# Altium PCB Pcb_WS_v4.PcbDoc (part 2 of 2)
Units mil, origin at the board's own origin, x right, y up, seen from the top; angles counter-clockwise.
Board outline 3890 x 3890 mil, 2 copper layers (Top Layer, Bottom Layer), stack 50.044 mil thick; 84 components, 65 nets, 260 pads, 445 vias.
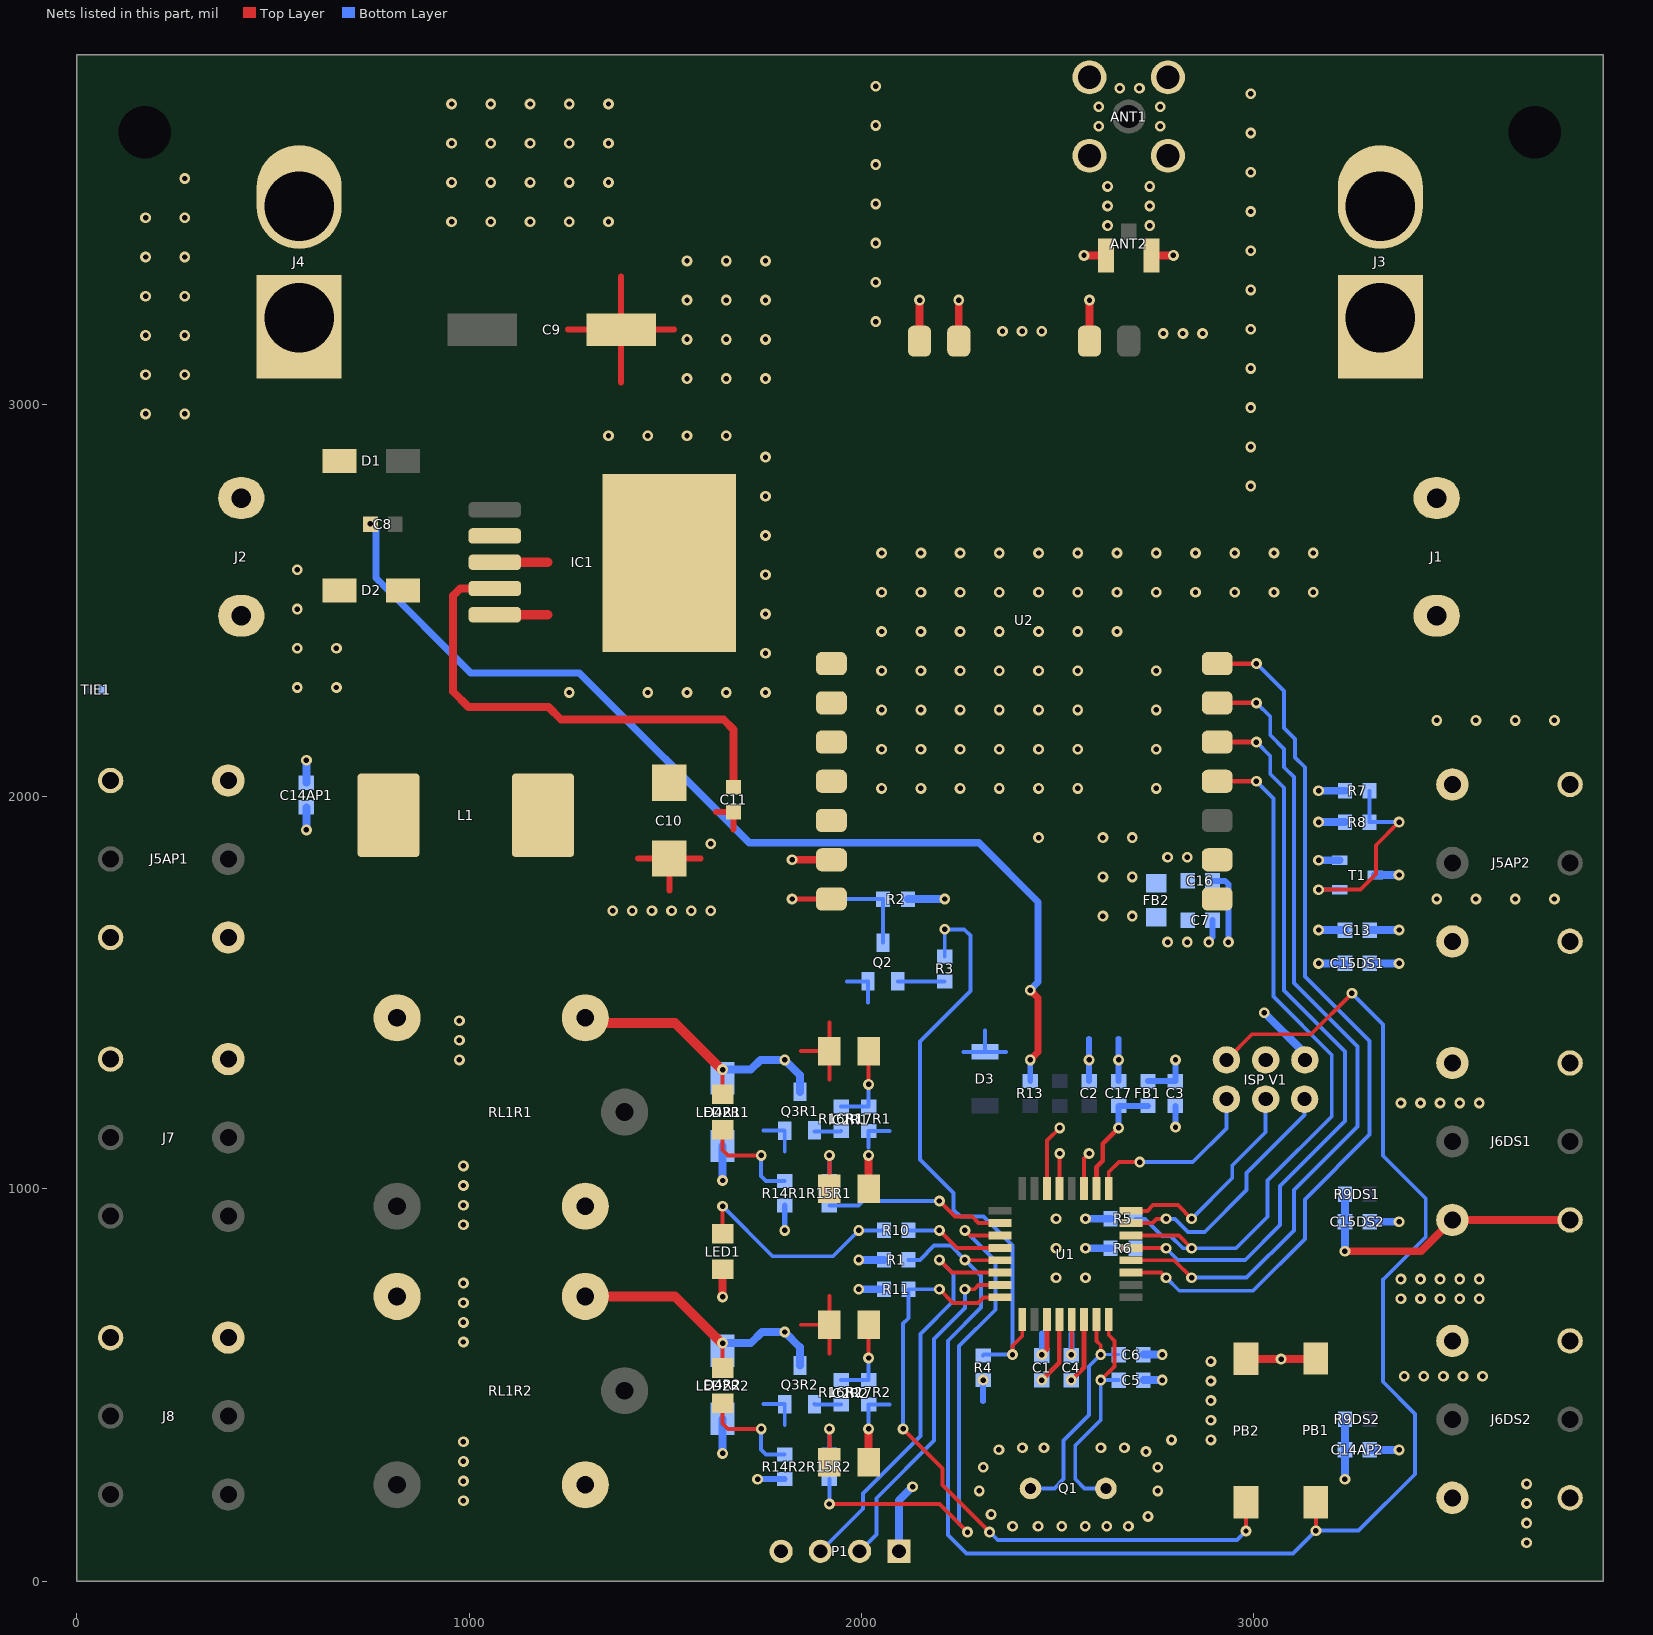
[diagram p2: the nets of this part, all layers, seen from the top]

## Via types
v1: diameter 27.56, hole 13.78, Top Layer to Bottom Layer, tented both sides, 369 vias
v2: diameter 20, hole 11.81, Top Layer to Bottom Layer, tented both sides, 76 vias

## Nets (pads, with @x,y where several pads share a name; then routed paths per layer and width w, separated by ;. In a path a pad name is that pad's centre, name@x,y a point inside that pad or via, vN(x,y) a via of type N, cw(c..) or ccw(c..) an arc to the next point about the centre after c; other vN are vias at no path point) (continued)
GND: "ISP V1.5" C1.2 C2.1 C3.2 C4.2 C5.2 C6.2 C7.1 C8.2 C9.2 C10.2 C11.2 C13.2 C14AP1.1 C14AP2.1 C15DS1.1 C15DS2.1 C16.1 C17.1 D2.2 D3.2 IC1.3 IC1.5 IC1.6 IC2R1.2 IC2R2.2 J2.1 J4.1 J5AP1.3 J5AP2.3 J6DS1.3 J6DS2.3 LED1.2 P1.4 PB1.2 PB2.2 Q2.2 Q3R1.2 Q3R2.2 R4.1 R5.2 R6.2 R7.1 R13.2 R17R1.1 R17R2.1 TIE1.1 U1.3 U1.5 U1.21 U2.7 U2.9 | length 6601.5
  Top Layer w9.84: U1.21@2504.06,1000.59 2504.06,1089.06 v1(2505,1090) ; v1(2534.61,577.18) 2535.55,578.13 U1.5@2535.55,666.59
  Top Layer w12: v1(2459.61,577.18) 2472.56,590.13 U1.3@2472.56,666.59
  Top Layer w15: 1251.93,3190 C9.2@1387.17,3190 ; 1387.17,3054.77 C9.2@1387.17,3190 ; 1387.17,3325.23 C9.2@1387.17,3190 ; 1430,1842.04 C10.2@1510,1842.04 1590,1842.04 ; 1510.45,1759.93 C10.2@1510.45,1839.93 ; 1522.4,3190 C9.2@1387.17,3190 ; 1629.05,1960.5 C11.2@1673.55,1960.5 1673.55,1916
  Top Layer w18: v1(2430,1328.39) 2450,1348.39 2450,1377.69 2450,1486 v1(2430,1506)
  Top Layer w20: v1(1645.86,724.46) LED1.2@1645.86,795 ; v1(1822.96,1838.49) U2.9@1922.96,1838.49 ; IC2R2.2@2017.86,303.06 v1(2017.86,387.87) ; IC2R1.2@2017.86,1000.34 v1(2017.86,1085.15) ; PB2.2@2979.87,566.56 2980.72,565.7 v1(3069.31,565.7) 3156.27,565.7 PB1.2@3157.89,567.33
  Top Layer w25: IC1.5@1065.04,2463.1 1200.27,2463.1 ; IC1.3@1065.04,2596.96 1200.27,2596.96
  Bottom Layer w10: 1750.16,451.1 Q3R2.2@1804.06,451.1 1804.06,397.2 ; 1750.16,1148.38 Q3R1.2@1804.06,1148.38 1804.06,1094.48 ; 1962.5,1528.58 Q2.2@2016.4,1528.58 2016.4,1474.68 ; v1(2017.86,387.87) R17R2.1@2017.86,449.74 2071.76,449.74 ; 2017.86,1105.65 R17R1.1@2017.86,1147.02 2071.76,1147.02 ; 2260.17,1349.12 D3.2@2314.07,1349.12 ; 2314.07,1403.02 D3.2@2314.07,1349.12 ; 2367.98,1349.12 D3.2@2314.07,1349.12
  Bottom Layer w15: 2309.61,458.28 v1(2309.61,512.18) ; R13.2@2430,1274.31 v1(2430,1328.39) ; v1(2459.61,577.18) 2459.61,631.08 ; v1(2534.61,577.18) 2534.61,631.08 ; C2.1@2580,1274.31 v1(2580,1328.39) 2580,1382.47 ; C17.1@2655,1274.32 v1(2655,1328.39) 2655,1382.47 ; v1(2800,1157.24) C3.2@2800,1211.32 ; v1(2885,1628.77) 2885,1632.17 2894.28,1641.44 C7.1@2894.28,1684.95 ; C16.1@2894.28,1784.92 2926.21,1784.92 2935,1776.13 v1(2935,1628.77)
  Bottom Layer w18: v1(748,2694.78) 748,2693.46 762,2679.46 762,2556.74 1003.74,2315 1280.5,2315 1713.5,1882 2299.33,1882 2450,1731.33 2450,1526.7 2430,1506.7 v1(2430,1506)
  Bottom Layer w20: C14AP1.1@585,2035 v1(585,2092.32) ; v1(2570.81,848.39) R6.2@2634.67,848.39 ; v1(2570.81,923.39) R5.2@2634.67,923.39 ; C5.2@2718.3,512.18 v1(2766.21,512.18) ; C6.2@2718.3,577.18 v1(2766.21,577.18) ; v1(3165,1574.46) C15DS1.1@3232.01,1574.46 ; v1(3165,1659.46) C13.2@3232.01,1659.46 ; v1(3165,2014.46) R7.1@3232.01,2014.46 ; C14AP2.1@3295,334.46 v1(3370,334.46) ; C15DS2.1@3295,915.77 v1(3370,915.77)
  other v1: 2385,140 2450,140 2510,140 2570,140 2625,140 2680,140 2730,165 2330,170 985,205 2300,230 2755,230 985,255 2310,290 2755,290 985,305 2725,330 2350,335 2410,340 2465,340 2610,340 2670,340 985,355 2790,360 2890.32,360.02 2890.32,410.02 2890.32,460.02 2890.32,510.02 3383,522 3433,522 3483,522 3533,522 3583,522 2890.32,560.02 985,609.51 985,659.51 985,709.51 3374.51,719.61 3424.51,719.61 3474.51,719.61 3524.51,719.61 3574.51,719.61 985,759.51 3374.51,769.61 3424.51,769.61 3474.51,769.61 3524.51,769.61 3574.51,769.61 2495.81,773.39 2570.81,773.39 2495.81,848.39 985,908.21 2495.81,923.39 985,958.21 985,1008.21 985,1058.21 3374.51,1218.65 3424.51,1218.65 3474.51,1218.65 3524.51,1218.65 3574.51,1218.65 975,1328.39 975,1378.39 975,1428.39 2615,1695 2690,1695 1365.62,1708.72 1415.62,1708.72 1465.62,1708.72 1515.62,1708.72 1565.62,1708.72 1615.62,1708.72 3465.86,1738.49 3565.86,1738.49 3665.86,1738.49 3765.86,1738.49 2615,1795 2690,1795 1615.62,1879.25 2451.06,1895 2615,1895 2690,1895 2051.06,2020.48 2151.06,2020.48 2251.06,2020.48 2351.06,2020.48 2451.06,2020.48 2551.06,2020.48 2751.06,2020.48 2051.06,2120.48 2151.06,2120.48 2251.06,2120.48 2351.06,2120.48 2451.06,2120.48 2551.06,2120.48 2751.06,2120.48 3465.86,2193.71 3565.86,2193.71 3665.86,2193.71 3765.86,2193.71 2051.06,2220.48 2151.06,2220.48 2251.06,2220.48 2351.06,2220.48 2451.06,2220.48 2551.06,2220.48 2751.06,2220.48 1255,2265 1455,2265 1555,2265 1655,2265 1755,2265 561.41,2277.57 661.41,2277.57 2051.06,2320.48 2151.06,2320.48 2251.06,2320.48 2351.06,2320.48 2451.06,2320.48 2551.06,2320.48 2751.06,2320.48 1755,2365 561.41,2377.57 661.41,2377.57 2051.06,2420.48 2151.06,2420.48 2251.06,2420.48 2351.06,2420.48 2451.06,2420.48 2551.06,2420.48 2651.06,2420.48 1755,2465 561.41,2477.57 2051.06,2520.48 2151.06,2520.48 2251.06,2520.48 2351.06,2520.48 2451.06,2520.48 2551.06,2520.48 2651.06,2520.48 2751.06,2520.48 2851.06,2520.48 2951.06,2520.48 3051.06,2520.48 3151.06,2520.48 1755,2565 561.41,2577.57 2051.06,2620.48 2151.06,2620.48 2251.06,2620.48 2351.06,2620.48 2451.06,2620.48 2551.06,2620.48 2651.06,2620.48 2751.06,2620.48 2851.06,2620.48 2951.06,2620.48 3051.06,2620.48 3151.06,2620.48 1755,2665 1755,2765 1755,2865 1355,2919.51 1455,2919.51 1555,2919.51 1655,2919.51 175,2975 275,2975 1555,3065 1655,3065 1755,3065 175,3075 275,3075 1555,3165 1655,3165 1755,3165 175,3175 275,3175 1555,3265 1655,3265 1755,3265 175,3275 275,3275 1555,3365 1655,3365 1755,3365 175,3375 275,3375 955,3465 1055,3465 1155,3465 1255,3465 1355,3465 175,3475 275,3475 955,3565 1055,3565 1155,3565 1255,3565 1355,3565 275,3575 955,3665 1055,3665 1155,3665 1255,3665 1355,3665 955,3765 1055,3765 1155,3765 1255,3765 1355,3765
GND-SOLAR: J1.2 J3.1
GND_ANT: ANT1.2 ANT2.2 U2.15 U2.16 U2.17 | length 425.1
  Top Layer w20: U2.15@2147.76,3160.54 v1(2147.76,3265) ; U2.16@2247.76,3160.54 v1(2247.76,3265) ; v1(2566.92,3379) ANT2.2@2622.76,3379 ; U2.17@2580.84,3160.54 v1(2580.84,3265) ; ANT2.2@2738.91,3379 v1(2794.75,3379)
  other v1: 2992,2791 2992,2891 2992,2991 2992,3091 2769.1,3180.06 2819.1,3180.06 2869.1,3180.06 2359.16,3185.88 2409.16,3185.88 2459.16,3185.88 2992,3191 2035.94,3210.36 2992,3291 2035.94,3310.36 2992,3391 2035.94,3410.36 2627.07,3455 2734.27,3455 2992,3491 2627.07,3505 2734.27,3505 2035.94,3510.36 2627.07,3555 2734.27,3555 2992,3591 2035.94,3610.36 2992,3691 2604.38,3708.09 2761.22,3708.09 2035.94,3710.36 2604.38,3758.09 2761.22,3758.09 2992,3791 2658.24,3804.81 2708.24,3804.81 2035.94,3810.36
LED: R10.1 U1.28 | length 251.5
  Top Layer w10: v1(2198.39,893.79) 2242.84,849.34 U1.28@2352.8,849.34
  Bottom Layer w10: R10.1@2119.71,893.79 v1(2198.39,893.79)
M0: U1.11 U2.1 | length 2271.3
  Top Layer w10: U1.11@2686.8,786.35 2763.26,786.35 v1(2776.21,773.39)
  Top Layer w12: U2.1@2906.43,2338.49 v1(3006.43,2338.49)
  Bottom Layer w10: v1(2776.21,773.39) 2809.61,740 2997.76,740 3130,872.24 3130,972.99 3295,1137.99 3295,1376.3 3130,1541.3 3130,2074.32 3104.99,2099.33 3104.99,2146.3 3076.66,2174.62 3076.66,2268.26 v1(3006.43,2338.49)
M1: U1.12 U2.2 | length 2102
  Top Layer w10: U1.12@2686.8,817.84 2796.76,817.84 v1(2841.21,773.39)
  Top Layer w12: U2.2@2906.43,2238.49 v1(3006.43,2238.49)
  Bottom Layer w10: v1(2841.21,773.39) 2981.3,773.39 3101.84,893.93 3101.84,996.54 3264.2,1158.9 3264.2,1362.2 3101.84,1524.56 3101.84,2049.15 3076.66,2074.32 3076.66,2121.29 3041.54,2156.41 3041.54,2203.37 v1(3006.43,2238.49)
MISO: "ISP V1.2" U1.16 | length 558.1
  Top Layer w10: U1.16@2686.8,943.83 2728.65,943.83 2743.21,958.39 2806.21,958.39 v1(2841.21,923.39)
  Bottom Layer w10: v1(2841.21,923.39) 2944.82,1027 2944.82,1058.82 3030,1144 3030,1228.39
MOSI: "ISP V1.3" U1.15 | length 650
  Top Layer w10: U1.15@2686.8,912.33 2741.13,912.33 2752.19,923.39 v1(2776.21,923.39)
  Bottom Layer w10: v1(2776.21,923.39) 2798.31,923.39 2831.71,890 2874.61,890 2981.3,996.69 2981.3,1040.05 3129,1187.75 3129,1228.39
NetC16_2: C16.2 FB2.2 U2.6
  other v1: 2780,1845 2830,1845
NetC17_2: C17.2 FB1.2 U1.18 | length 309.1
  Top Layer w12: U1.18@2598.54,1000.59 2598.54,1054.92 2615,1071.38 2615,1115 v1(2655,1155)
  Bottom Layer w15: v1(2655,1155) C17.2@2655,1211.32 FB1.2@2730,1211.32
NetD2_1: D2.1 IC1.2 L1.1
NetD4R1_2: D4R1.2 LED2R1.2 Q3R1.3 RL1R1.4 | length 728.5
  Top Layer w10: LED2R1.2@1645.86,1240.54 v1(1645.86,1303.81)
  Top Layer w25: RL1R1.4@1295.86,1422.82 1524.46,1422.82 v1@1643.47,1303.81
  Bottom Layer w20: D4R1.2@1643.47,1303.81 v1(1645.86,1303.81) 1717.53,1303.81 1742.11,1328.39 v1(1804.06,1328.39) 1842.66,1289.8 Q3R1.3@1842.66,1246.8
NetD4R2_2: D4R2.2 LED2R2.2 Q3R2.3 RL1R2.4 | length 734
  Top Layer w10: LED2R2.2@1645.86,543.26 v1(1645.86,606.53)
  Top Layer w25: RL1R2.4@1295.86,725.54 1524.46,725.54 v1@1643.47,606.53
  Bottom Layer w20: D4R2.2@1643.47,606.53 1717.53,606.53 1746,635 v1(1804.06,635) 1842.66,596.4 Q3R2.3@1842.66,549.52
NetIC2R1_1: IC2R1.1 R15R1.2 | length 149.9
  Top Layer w10: IC2R1.1@1917.86,1000.34 v1(1917.86,1085.15)
  Bottom Layer w10: R15R1.2@1917.86,1020.01 v1(1917.86,1085.15)
NetIC2R2_1: IC2R2.1 R15R2.2 | length 149.9
  Top Layer w10: IC2R2.1@1917.86,303.06 v1(1917.86,387.87)
  Bottom Layer w10: R15R2.2@1917.86,322.73 v1(1917.86,387.87)
NetLED1_1: LED1.1 R10.2 | length 561.5
  Top Layer w10: LED1.1@1645.86,885 v1(1645.86,955.54)
  Bottom Layer w10: v1(1645.86,955.54) 1773.4,828 1927.07,828 v1(1992.86,893.79) R10.2@2056.72,893.79
NetLED2R1_1: LED2R1.1 R14R1.2 | length 273.2
  Top Layer w10: LED2R1.1@1645.86,1150.54 1645.86,1099.14 1659.86,1085.14 v1(1744.06,1085.14)
  Bottom Layer w10: v1(1744.06,1085.14) 1744.06,1032.6 1756.65,1020.01 R14R1.2@1804.06,1020.01
NetLED2R2_1: LED2R2.1 R14R2.2 | length 273.2
  Top Layer w10: LED2R2.1@1645.86,453.26 1645.86,401.86 1659.86,387.87 v1(1744.06,387.87)
  Bottom Layer w10: v1(1744.06,387.87) 1744.06,335.32 1756.65,322.73 R14R2.2@1804.06,322.73
NetQ2_1: Q2.1 R3.2 | length 119.9
  Bottom Layer w10: Q2.1@2092.2,1528.8 R3.2@2212.06,1528.8
NetQ3R1_1: Q3R1.1 R16R1.2 | length 68.4
  Bottom Layer w10: Q3R1.1@1879.86,1146.01 1946.85,1146.01 R16R1.2@1947.86,1147.02
NetQ3R2_1: Q3R2.1 R16R2.2 | length 68.7
  Bottom Layer w10: Q3R2.1@1879.86,451.31 1881.43,449.74 R16R2.2@1947.86,449.74
NetR7_2: R7.2 R8.2 T1.1 | length 527.4
  Top Layer w10: v1(3165,1762.33) 3271.14,1762.33 3311.13,1802.32 3311.13,1875.59 v1(3370,1934.46)
  Bottom Layer w10: v1(3165,1762.33) T1.1@3218.23,1762.33 ; R7.2@3295,2014.46 R8.2@3295,1934.46 v1(3370,1934.46)
NetU1_19: U1.19 | length 94.8
  Top Layer w10: U1.19@2567.05,1000.59 2567.05,1077.05 v1(2580,1090)
NetU1_22: U1.22 | length 167.8
  Top Layer w10: U1.22@2472.56,1000.59 2472.56,1122.56 v1(2505,1155)
NetU2_10: U2.10
NetU2_11: U2.11
NetU2_12: U2.12
NetU2_13: U2.13
NetU2_14: U2.14
OPEN1: J7.1 RL1R1.3
OPEN2: J8.1 RL1R2.3
P5V-Main: "ISP V1.6" C1.1 C3.1 C4.1 C7.2 C10.1 C11.1 D4R1.1 D4R2.1 FB1.1 FB2.1 IC1.4 IC2R1.4 IC2R2.4 L1.2 P1.1 R1.1 R2.2 R8.1 R11.1 R14R1.1 R14R2.1 RL1R1.5 RL1R2.5 T1.2 U1.4 U1.6 | length 3154.2
  Top Layer w10: 1845,653.46 IC2R2.4@1917.86,653.46 ; 1845,1350.74 IC2R1.4@1917.86,1350.74 ; 1917.86,580.6 IC2R2.4@1917.86,653.46 ; 1917.86,726.32 IC2R2.4@1917.86,653.46 ; 1917.86,1277.88 IC2R1.4@1917.86,1350.74 ; 1917.86,1423.59 IC2R1.4@1917.86,1350.74
  Top Layer w12: v1(2459.61,512.18) 2504.06,556.63 U1.4@2504.06,666.59 ; v1(2534.61,512.18) 2567.05,544.62 U1.6@2567.05,666.59
  Top Layer w20: IC1.4@1065.04,2530.03 977.03,2530.03 959,2512 959,2267.02 998.02,2228 1202,2228 1234.23,2195.77 1648.39,2195.77 1673.55,2170.61 C11.1@1673.55,2023.5
  Bottom Layer w15: v1(1735,259.74) R14R2.1@1804.06,259.74 ; v1(1804.06,893.79) R14R1.1@1804.06,957.02 ; FB1.1@2730,1274.32 C3.1@2800,1274.32 v1(2800,1328.39)
  Bottom Layer w20: v1(1645.86,325.47) D4R2.1@1645.86,413.39 ; v1(1645.86,1021.01) D4R1.1@1645.86,1108.93 ; v1(1992.86,743.79) R11.1@2056.72,743.79 ; v1(1992.86,818.79) R1.1@2056.72,818.79 ; P1.1@2095,76 2095,205.55 v1(2130,240.55) ; R2.2@2117.99,1738.49 v1(2212.06,1738.49) ; v1(3026.21,1448.39) 3130,1344.6 3130,1328.39 ; v1(3165,1837.14) T1.2@3218.23,1837.14 ; v1(3165,1934.46) R8.1@3232.01,1934.46
  other v1: 2780,1628.77 2830,1628.77
P5V-SEN: C13.1 C14AP1.2 C14AP2.2 C15DS1.2 C15DS2.2 J5AP1.1 J5AP2.1 J6DS1.1 J6DS2.1 R9DS1.2 R9DS2.2 T1.3 | length 1173.8
  Top Layer w20: v1(3232.01,840.77) 3426.09,840.77 J6DS1.1@3505.86,920.54 J6DS1.1@3805.86,920.54
  Bottom Layer w20: v1(585,1914.69) C14AP1.2@585,1972.01 ; v1(3232.01,259.46) C14AP2.2@3232.01,334.46 R9DS2.2@3232.01,412.26 ; v1(3232.01,840.77) C15DS2.2@3232.01,915.77 R9DS1.2@3232.01,986.31 ; C15DS1.2@3295,1574.46 v1(3370,1574.46) ; C13.1@3295,1659.46 v1(3370,1659.46) ; T1.3@3308.78,1799.74 v1(3370,1799.74)
  other v1: 3695,97.74 3695,147.74 3695,197.74 3695,247.74
P12V-BAT: D1.2 J2.2 J4.2
P16V-SOLAR: J1.1 J3.2
RESET-E32: R3.1 R4.2 U1.1 | length 1571.2
  Top Layer w10: v1(2384.61,577.18) 2384.61,599.79 2409.57,624.75 U1.1@2409.57,666.59
  Bottom Layer w9.84: R3.1@2212.06,1591.79 v1(2212.06,1661.26)
  Bottom Layer w10: v1(2212.06,1661.26) 2261.59,1661.26 2277.53,1645.32 2277.53,1503.75 2148.79,1375.01 2148.79,1074.97 2234.61,989.15 2234.61,945.77 2251.6,928.79 2311.16,928.79 2384.61,855.34 v1(2384.61,577.18) 2311.61,577.18 R4.2@2309.61,575.17
RL-CT-QR1: IC2R1.3 R16R1.1 R17R1.2 | length 210.7
  Top Layer w10: v1(2017.86,1265.93) IC2R1.3@2017.86,1350.74
  Bottom Layer w10: R16R1.1@1947.86,1210.01 R17R1.2@2017.86,1210.01 v1(2017.86,1265.93)
RL-CT-QR2: IC2R2.3 R16R2.1 R17R2.2 | length 210.7
  Top Layer w10: v1(2017.86,568.65) IC2R2.3@2017.86,653.46
  Bottom Layer w10: R16R2.1@1947.86,512.73 R17R2.2@2017.86,512.73 v1(2017.86,568.65)
RL-CTL1: R15R1.1 U1.26 | length 463.2
  Top Layer w10: v1(2198.39,968.79) 2238.39,928.79 2282.02,928.79 2298.48,912.33 U1.26@2352.8,912.33
  Bottom Layer w10: R15R1.1@1917.86,957.02 1991.67,957.02 2003.44,968.79 v1(2198.39,968.79)
RL-CTL2: R15R2.1 U1.27 | length 1388.2
  Top Layer w10: v1(1917.86,196.51) 2198.49,196.51 v1(2270,125) ; v1(2263.39,893.79) 2276.35,880.83 U1.27@2352.8,880.83
  Bottom Layer w10: v1(1917.86,196.51) R15R2.1@1917.86,259.74 ; v1(2263.39,893.79) 2341.63,815.55 2341.63,691.63 2248.78,598.78 2248.78,146.22 v1(2270,125)
RST-E32: Q2.3 R2.1 U2.8 | length 443.5
  Top Layer w12: v1(1822.96,1738.49) U2.8@1922.96,1738.49
  Bottom Layer w10: v1(1822.96,1738.49) R2.1@2055,1738.49 Q2.3@2055,1627.01
RST_MCU: "ISP V1.4" PB1.1 R1.2 U1.29 | length 4156.8
  Top Layer w10: v1(2263.39,818.79) 2264.34,817.84 U1.29@2352.8,817.84 ; 2930,1328.39 2995.41,1393.8 3145.26,1393.8 v1(3249.65,1498.2) ; v1(3157.89,128.46) PB1.1@3157.89,201.19
  Bottom Layer w10: R1.2@2119.71,818.79 2148.79,818.79 2185,855 2227.18,855 v1(2263.39,818.79) 2304.79,777.39 2304.79,697.4 2220,612.61 2220,117.62 2267.62,70 3099.43,70 v1(3157.89,128.46) 3266.66,128.46 3410.58,272.37 3410.58,426.31 3328.7,508.18 3328.7,768.19 3437.96,877.45 3437.96,975.04 3328.8,1084.19 3328.8,1419.05 v1(3249.65,1498.2)
RXD-E32: R6.1 U1.13 U2.3 | length 2000.7
  Top Layer w10: U1.13@2686.8,849.34 2775.27,849.34 v1(2776.21,848.39)
  Top Layer w12: U2.3@2906.43,2138.49 v1(3006.43,2138.49)
  Bottom Layer w10: R6.1@2697.66,848.39 v1(2776.21,848.39) 2805.82,818.79 2977.86,818.79 3067,907.92 3067,1007.31 3232.01,1172.32 3232.01,1350.17 3076.66,1505.51 3076.66,2022.11 3041.54,2057.22 3041.54,2103.37 v1(3006.43,2138.49)
RXM: P1.3 U1.30 | length 1066.3
  Top Layer w10: v1(2198.39,818.79) 2230.83,786.35 U1.30@2352.8,786.35
  Bottom Layer w10: P1.3@1895,76 2003.44,184.44 2003.44,223.44 2150,370 2150,630 2234.61,714.61 2234.61,782.57 v1(2198.39,818.79)
SCK: "ISP V1.1" U1.17 | length 462.4
  Top Layer w10: U1.17@2630.04,1000.59 2630.04,1042.43 2655.61,1068 v1(2709,1068)
  Bottom Layer w10: v1(2709,1068) 2844,1068 2930,1154 2930,1228.39
TXD-E32: R5.1 U1.14 U2.4 | length 1926.4
  Top Layer w10: U1.14@2686.8,880.83 2808.77,880.83 v1(2841.21,848.39)
  Top Layer w12: U2.4@2906.43,2038.49 v1(3006.43,2038.49)
  Bottom Layer w10: R5.1@2697.66,923.39 2722.59,923.39 2765.98,880 2787.28,880 2818.89,848.39 v1(2841.21,848.39) 2954.61,848.39 3034.9,928.69 3034.9,1020.64 3198.31,1184.04 3198.31,1341.29 3050,1489.6 3050,1994.92 v1(3006.43,2038.49)
TXM: P1.2 U1.31 | length 873
  Top Layer w10: v1(2263.39,743.79) 2287.41,743.79 2298.48,754.85 U1.31@2352.8,754.85
  Bottom Layer w10: P1.2@1995,76 2038.25,119.25 2038.25,211.2 2185,357.95 2185,617.5 2263.39,695.89 v1(2263.39,743.79)
WAKE: PB2.1 R11.2 U1.32 | length 1713.4
  Top Layer w10: v1(2105.83,387.87) 2206.2,287.5 2206.2,245.15 v1(2326.35,125) ; v1(2198.39,743.79) 2233.39,708.79 2296.39,708.79 2310.96,723.35 U1.32@2352.8,723.35 ; v1(2979.87,127.69) PB2.1@2979.87,200.42
  Bottom Layer w10: v1(2105.83,387.87) 2105.83,656.12 2119.71,670 R11.2@2119.71,743.79 v1(2198.39,743.79) ; v1(2326.35,125) 2327.05,125 2347.05,105 2957.17,105 v1(2979.87,127.69)
XTAL1: C6.1 Q1.1 U1.7 | length 590.6
  Top Layer w10: U1.7@2598.54,666.59 2598.54,612.26 2609.61,601.2 v1(2609.61,577.18)
  Bottom Layer w8: v1(2609.61,577.18) C6.1@2655.31,577.18
  Bottom Layer w10: Q1.1@2430.49,236.12 2491.32,236.12 2514.95,259.74 2514.95,358.04 2580,423.09 2580,547.57 v1(2609.61,577.18)
XTAL2: C5.1 Q1.2 U1.8 | length 587.9
  Top Layer w10: v1(2609.61,512.18) 2644.61,547.18 2644.61,612.26 2630.04,626.83 U1.8@2630.04,666.59
  Bottom Layer w10: Q1.2@2622.61,236.12 2568.17,236.12 2544.55,259.74 2544.55,345.77 2609.61,410.83 v1(2609.61,512.18) C5.1@2655.31,512.18
pads on no net: HOLE1.1 HOLE2.1

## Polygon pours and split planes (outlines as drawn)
GND on Top Layer "GND_L01_P027" (solid, remove dead copper, pour order 27): 1715,1900 1715,1992 1850,1992 1850,2675 1900,2675 1900,3855 35,3855 35,2250 650,2250 650,1650 1650,1650 1650,1900
GND on Top Layer "GND_L01_P039" (solid, pour order 39): 2747.69,390.57 2724.53,367.42 2304.46,367.42 2276.35,339.3 2276.35,189.25 2340.6,125 2722.11,125 2775.27,178.16 2775.27,291.35 2804.55,320 2985,320 3855,320 3855,2238.49 3200,2238.49 3200,2675 2000,2675 2000,1968 2254.83,1968 2293.8,1929.02 2293.8,1706.46 2328.2,1672.07 2719.49,1672.07 2735.41,1687.99 2735.41,1865.47 2764.67,1894.73 2837.23,1894.73 2849.99,1907.49 2849.99,1962.43 2855.82,1968 3191.79,1968 3191.79,1813 3101.84,1813 3101.84,1402.15 2841.21,1402.15 2841.21,1131.63 2931.03,1131.63 2931.03,595.81 2747.69,595.81
P5V-Main on Top Layer "P5V-MAIN_L01_P035" (solid, pour order 35): 2269.9,176.44 2270,344.97 2298.92,373.9 2723.16,373.9 2737.18,387.92 2736.81,391.87 2736.81,609.25 2930,609.25 2930,1131.63 2824.07,1131.63 2824.07,1423.59 3101.84,1423.59 3101.84,1813 3191.79,1813 3191.79,1954.85 3065.58,1954.85 2985,1874.27 2985,1606.21 2963.16,1584.37 2867.05,1584.37 2845,1606.42 2845,1648.13 2839.2,1653.94 2318.29,1653.94 2282.02,1690.21 2282.02,1921.81 2248.97,1954.85 1864,1954.85 1842.96,1975.89 1842.96,2120 1730.29,2120 1730.29,1954.85 1715,1954.85 1715,1900 1659.86,1900 1659.86,1650 1320,1650 1320,1600 1187.95,1600 1187.95,176.44
P5V-SEN on Top Layer "P5V-SEN_L01_P031" (solid, remove dead copper, pour order 31): 2301.7,150 2346.7,105 2729.26,105 2790.63,166.37 2790.63,277.18 2806.21,292.76 3855,292.76 3855,35 3290,35 3164.52,35 3164.52,160.48 3020.48,160.48 2975,160.48 2975,35 2172.09,35 2146.6,60.49 1055,60.49 1055,1425 985,1495 566.9,1495 484.78,1577.12 484.78,1916 448.78,1952 60.49,1952 40,1972.49 40,2095 80,2135 590.99,2135 615.98,2110 615.98,1600 1187.95,1600 1187.95,176.44 2196.56,176.44 2223,150
GND on Top Layer "GND_L01_P040" (solid, pour order 40): 795,1296.63 925,1166.63 925,994.62 925,35 1055,35 1055,1495 564.28,1495 485.95,1576.25 485.95,1755 35,1755 35,1428.39 533.23,1428.39 665,1296.63
GND_ANT on Top Layer "GND_ANT_L01_P037" (solid, pour order 37): 2000,3829.51 2000,2775 3025,2775 3025,3829.51
GND-SOLAR on Top Layer "GND-SOLAR_L01_P028" (solid, remove dead copper, pour order 28): 3300,2775 3125,2775 3125,3855 3855,3855 3855,2310 3300,2310
GND on Bottom Layer "GND-Bottom" (solid, remove dead copper, pour order 38): 3432.98,1830.54 3432.98,1710 3855,1710 3855,2240 3200,2240 3200,2675 1900,2675 1900,3855 35,3855 35,35 3630,35 3630,1481.48 3365.37,1481.48 3365.37,1830.54
P5V-SEN on Bottom Layer "P5V-SEN_L02_P030" (solid, remove dead copper, pour order 30): 3511.97,1493 3606.95,1493 3630,1469.95 3630,336.82 3630,35 3845,35 3845,1680 3830,1695 3432.69,1695 3417.69,1710 3417.69,1830.54 3365.37,1830.54 3365.37,1505.51 3377.88,1493
GND_ANT on Bottom Layer "GND_ANT_L02_P033" (solid, pour order 33): 2000,3829.51 2000,2775 3025,2775 3025,3829.51
P16V-SOLAR on Bottom Layer "P16V-SOLAR_L02_P029" (solid, pour order 29): 3300,2775 3125,2775 3125,3862.5 3862.5,3862.5 3862.5,2310 3300,2310

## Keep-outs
Bottom Layer:
  region: 3864.91,2241.96
Keep-Out Layer:
  the board outline again, w5

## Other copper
Top Layer:
  pour cut-out: 2515,492 ccw(c2515,501) 2524,501 2524,512 2545,512 2545,501 ccw(c2554,501) 2554,492 2609.61,492 2609.61,577.18 2370.19,577.18 2370.19,498 2384,498 2384,492 2441,492 ccw(c2441,500) 2449,500 2449,512 2470,512 2470,500 ccw(c2478,500) 2478,492
  pour cut-out: 2669.42,1120 2703,1086.42 2703,1083 2657.68,1082.73 2649.4,1090 2430,1090 2430,1175.39 2655,1175.39 2655,1168.79 2669.42,1168.79
  region net GND: 2875,1750 2875,1669.03 2870,1664.03 2870,1616.08 2876.96,1609.12 2943.04,1609.12 2951.06,1617.14 2951.06,1656.94 2938.8,1669.2 2938.8,1750
  region: 2875,1750
  region net NetC16_2: 2920,1860 2851.98,1860 2848,1863.98 2771.45,1863.98 2765,1857.53 2765,1820 2770,1815 2920,1815
  pour cut-out: 2946.04,1868.27 2946.04,1808.72 2866.81,1808.72 2866.81,1868.27
  region net EARTH: 15,15 3875,14.82 3875,3875.04 2890,3875 2890,3855 3855,3855 3855,35 35,35 35,3855 2480,3855 2480,3875 15,3875
  pour cut-out: 2945.7,610.02 3013.34,610.02 3013.34,523.02 2945.7,523.02
  pour cut-out: 3192.06,523.87 3124.42,523.87 3124.42,610.87 3192.06,610.87
  pour cut-out: 2946.04,1768.27 2946.04,1708.72 2866.81,1708.72 2866.81,1768.27
  region net GND: 2410,945 2410,723.35 2630.04,723.35 2630.04,943.83
  pour cut-out: 2600,3425 2761.22,3425 2761.22,3334.04 2600,3334.04
  pour cut-out: 2551.06,3200.16 2610.61,3200.16 2610.61,3120.92 2551.06,3120.92
  pour cut-out: 2217.99,3200.16 2277.54,3200.16 2277.54,3120.92 2217.99,3120.92
  pour cut-out: 2117.99,3200.16 2177.54,3200.16 2177.54,3120.92 2117.99,3120.92
  pour cut-out: 2905,1880
  pour cut-out: 2905,1880
  pour cut-out: 2384.57,968.83 2655.04,968.83 2655.04,698.35 2384.57,698.35
  pour cut-out: 1874.31,354.48 2061.4,354.48 2061.4,251.65 1874.31,251.65
  pour cut-out: 2061.4,1402.15 2061.4,1299.32 1880,1299.32 1880,1402.15
  pour cut-out: 1603.36,1280.54 1688.36,1280.54 1688.36,1110.54 1603.36,1110.54
  pour cut-out: 1603.36,925 1688.36,925 1688.36,755 1603.36,755
  pour cut-out: 1688.36,583.26 1603.36,583.26 1603.36,413.26 1688.36,413.26
  pour cut-out: 2061.4,602.04 2061.4,704.87 1880,704.87 1880,602.04
  pour cut-out: 2178,743.79 2178,968.79 2183.97,968.79 2183.97,983.21 2263.39,983.21 2263.39,743.79
  pour cut-out: 2855,698.39 2861.6,698.39 2861.6,923.39 2776.21,923.39 2776.21,683.97 2855,683.97
  pour cut-out: 2384.57,968.83
  region net BAT-VSEN: 785,2672.5 794.5,2663 905,2663 952,2710 1127.5,2710 1140,2722.5 1140,3242.01 1117.01,3265 853.72,3265 785,3196.28 785,2945 759.51,2919.51 759.51,2787.55 785,2762.06
  region net P12V-BAT: 290,2869.68 385.86,2965.54 385.86,3302.68 419.18,3336 717.06,3336 759.51,3293.55 759.51,2968.37 732.5,2941.36 732.5,2790.64 708.42,2766.55 605.99,2766.55 561.41,2721.98 561.41,2664.22 530.56,2633.38 331.95,2633.38 290,2675.33
  pour cut-out: 880,2182 1100,2182 1320,2182 1320,1650 690,1650 690,2182
  pour cut-out: 777.2,2411.28 777.2,2760 1165.49,2760 1165.49,2411.28
  region net P5V-Main: 1100,1840 1120,1820 1200,1820 1320,1820 1360,1860 1360,1940 1390,1970 1430,1970 1580,1970 1610,2000 1832.96,2000 1842.96,2010 1842.96,2110 1832.96,2120 1157.5,2120 1100,2062.5 1100,2040.54
  region net NetD2_1: 957,2685 1126,2685 1133.75,2677.25 1133.75,2649.75 1127,2643 988,2643 926,2581 926,2228 880,2182 880,1850 865,1835 715,1835 690,1860 690,2230.55 775,2315.55 775,2623.75 794.25,2643 915,2643
  region: 0,3890
  region: 982.01,1106.11
  pour cut-out: 3920.54,1420.95
  pour cut-out: 3920.54,1420.95
  region: 310.86,2890.54
Bottom Layer:
  pour cut-out: 2710,1585.7 2710,1886.07 2870.49,1886.07 2870.49,1820.69 2922.98,1820.69 2922.98,1655.27 2870.49,1655.27 2870.49,1585.7
  region net NetC16_2: 2736.51,1760 2736.51,1812.51 2741.14,1817.14 2757.89,1817.14 2765,1824.24 2765,1854.26 2771.32,1860.58 2837.03,1860.58 2845,1852.61 2845,1770 2800,1770 2790,1760
  region net P5V-Main: 2736.51,1711.05 2736.51,1659.43 2742.03,1653.91 2757.89,1653.91 2765,1646.8 2765,1620.5 2773.72,1611.78 2837.03,1611.78 2845,1619.75 2845,1701.05 2800,1701.05 2790,1711.05
  region: 2725,1770
  region net EARTH: 15,15 3875,14.82 3875,3875.04 2890,3875 2890,3855 3855,3855 3855,35 35,35 35,3855 2480,3855 2480,3875 15,3875
  pour cut-out: 3199.29,446.95 3327.72,446.95 3327.72,299.78 3198.31,299.78
  pour cut-out: 550.31,2068.7 550.31,1950 615.98,1950 615.98,2068.7
  pour cut-out: 2621.61,611.86 2621.61,477.49 2791.4,477.49 2791.4,611.86
  pour cut-out: 2024,968.79 2152.42,968.79 2152.43,709.1 2024,709.1
  pour cut-out: 650,1500 923.39,1500 923.39,1265.93 1460,1265.93 1460,1120 935,1120 935,555.93 1460,555.93 1460,410 935,410 935,35 35,35 35,1410 650,1410
  pour cut-out: 2730.38,813.71 2545.32,813.71 2545.32,958.08 2730.38,958.08
  pour cut-out: 2834.69,1177.62 2834.69,1351.33 2395.32,1351.33 2395.32,1177.62
  pour cut-out: 2358.52,1319.43 2269.69,1319.43 2269.69,1380.88 2358.52,1380.88
  pour cut-out: 2052.54,1114.3 1982.54,1114.3 1982.54,1242.73 2052.54,1242.73
  pour cut-out: 1830.79,1155 1830.79,1109.97 1777.33,1109.97 1777.33,1182 1830.79,1182
  pour cut-out: 3200.39,881.09 3327.72,881.09 3327.72,1021 3200.39,1021
  pour cut-out: 2045,1540 2045,1490.17 1989.67,1490.17 1989.67,1562.2 2045,1562.2
  pour cut-out: 1830.79,489.93 1830.79,412.69 1777.33,412.69 1777.33,489.93
  pour cut-out: 2052.54,545.45 2052.54,417.02 1982.54,417.02 1982.54,545.45
  pour cut-out: 3324.51,1694.15 3324.51,1539.78 3150.39,1539.78 3150.39,1694.15
  pour cut-out: 3327.72,2049.15 3327.72,1899.78 3150.39,1899.78 3150.39,2049.15
  pour cut-out: 2564.29,478.48 2267.62,478.48 2267.62,603.87 2564.29,603.87
  region net CLOSE1: 675,990 725,1040 887.6,1040 900,1027.6 900,890 890,880 59,880 46.49,892.51 46.49,980 56.49,990
  region net OPEN1: 58,1410 550,1410 640,1500 890,1500 900,1490 900,1360 890,1350 650,1350 570,1270 58,1270 47,1281 47,1399
  region net COM1: 55.75,1190 603.57,1190 679.51,1265.93 1440.87,1265.93 1460,1246.8 1460,1133.54 1446.46,1120 688.57,1120 638.57,1070 60,1070 45,1085 45,1179.25
  region net COM2: 55.75,480 603.57,480 679.51,555.93 1440.87,555.93 1460,536.8 1460,423.54 1446.46,410 688.57,410 638.57,360 60,360 45,375 45,469.25
  region net OPEN2: 58,700 550,700 650,800 890,800 900,790 900,650 890,640 650,640 570,560 58,560 47,571 47,689
  region net CLOSE2: 675,280 725,330 887.6,330 900,317.6 900,180 890,170 59,170 46.49,182.51 46.49,270 56.49,280
Multi-Layer:
  pour cut-out: 2480,3855 35,3855 35,35 3855,35 3855,3855 2890,3855 2890,3829.51 3829.51,3829.51 3829.51,60.49 60.49,60.49 60.49,3829.51 2480,3829.51
  pour cut-out: 1850.99,3855 2000,3855 2000,2775 3025,2775 3025,2675 1850.99,2675
  pour cut-out: 1900,2675 1850,2675 1850,2145.49 2000,2145.49 2000,2675
  pour cut-out: 35,2250 690,2250 690,1650 1466.2,1650 1466.2,1600 615.98,1600 615.98,2200 35,2200
  pour cut-out: 3855,2310 3855,2240 3200,2240 3200,2675 3025,2675 3025,3855 3125,3855 3125,2775 3300,2775 3300,2310

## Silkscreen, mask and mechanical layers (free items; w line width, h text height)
Top Overlay:
  text "-" at 453.14,3701.01 h393.7
  text "-" at 3209.05,3701.01 h393.7
  text "SENSOR NODE / V3.1" at 1830,3617 h47.24
  text "FEMALE" at 3112.5,3125 h70.87 r90
  text "FEMALE" at 844,3120 h70.87 r90
  text "+BAT" at 310,2930 h120
  text "+SOLAR" at 3442.39,2920 h118.11
  text "+" at 614.07,2728.34 h196.85 r90
  text "+" at 3380.32,2715 h196.85 r90
  text "-" at 3365,2390 h275.59 r90
  text "-" at 614.07,2324.23 h275.59 r90
  text "-" at 455,2170 h275.59 r90
  text "GND" at 3326.48,1988.01 h30 r90
  text "P5V" at 615.98,1987.01 h30 r90
  text "DT_AP" at 3326.48,1752 h30 r90
  text "DT_AP" at 615.98,1751 h30 r90
  text "P5V" at 3326.48,1567.05 h30 r90
  text "GND" at 610.99,1566.05 h30 r90
  text "RST" at 2948,1407 h30 r90
  text "G" at 3042.76,1407 h30 r90
  text "V5V" at 3145.89,1407 h30 r90
  text "GND" at 3326.48,1300.55 h30 r90
  text "OPEN" at 610,1241 h30 r90
  text "SCK" at 2944.34,1074 h30 r90
  text "COM" at 610,1071 h30 r90
  text "DT_DS" at 3326.48,1064.54 h30 r90
  text "MISO" at 3042.76,1053.59 h30 r90
  text "MOSI" at 3151.89,1053.59 h30 r90
  text "P5V" at 3326.48,879.59 h30 r90
  text "CLOSE" at 610,857 h30 r90
  text "RESET" at 3168,648 h30 r90
  text "WAKE" at 3009.39,642 h30 r90
  text "GND" at 3326.48,580.37 h30 r90
  text "OPEN" at 610,535 h30 r90
  text "COM" at 610,355 h30 r90
  text "DT_DS" at 3326.48,344.35 h30 r90
  text "P5V" at 3326.48,159.4 h30 r90
  text "G" at 1817,140 h30 r90
  text "RX" at 1914.91,140 h30 r90
  text "TX" at 2017.86,140 h30 r90
  text "V5V" at 2117,140 h30 r90
  text "CLOSE" at 610,126 h30 r90
Bottom Overlay:
  lines w6: 1787,2773 1787,3123 2961,3123 2961,2773 1787,2773
  text "SN:" at 2908,2826 h60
